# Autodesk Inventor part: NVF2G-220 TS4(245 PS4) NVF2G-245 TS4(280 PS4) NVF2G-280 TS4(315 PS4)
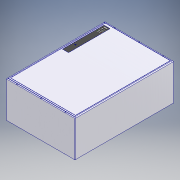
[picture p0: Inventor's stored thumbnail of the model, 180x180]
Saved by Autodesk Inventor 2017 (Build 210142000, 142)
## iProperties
Part Number: NVF2G-220 TS4(245 PS4) NVF2G-245 TS4(280 PS4) NVF2G-280 TS4(315 PS4)
Material: Типовые
Document SubType Name: Modeling
Designer: RSagdiev
Density: 1 g/cm^3
Appearance: По умолчанию
Author: RSagdiev
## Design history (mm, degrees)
sketch "Эскиз1"
  geometry: L1 (0, 0)-(44.679, 0) reference; L2 (0, 0)-(0, 56.035) reference; L3 (0, 0)-(1020, 0); L4 (1020, 0)-(1020, 370.6); L5 (1020, 370.6)-(0, 370.6); L6 (0, 370.6)-(0, 0)
  constraints: 12 end point, 3 horizontal, 2 parallel, 2 vertical, 1 perpendicular
  dimensions: "d0" = 1020 distance of L5.end L4.end; "d1" = 370.6 distance of L4.end L3.end
extrude "Выдавливание1" new body sketch "Эскиз1" stored distance "d2" = 710; taper "d3" = 0 deg
sketch "Эскиз2"
  geometry: L1 (0, 0)-(0, 1020) reference; L2 (710, 0)-(710, 1020) reference; L3 (0, 1020)-(150, 1020); L4 (710, 1020)-(710, 1008); L5 (710, 0)-(560, 0); L6 (0, 0)-(0, 12); L7 (0, 1020)-(710, 1020) reference; L8 (0, 1020)-(150, 1020); L9 (150, 1020)-(150, 1008); L10 (150, 1008)-(0, 1008); L11 (0, 1008)-(0, 1020); L12 (710, 1020)-(560, 1020); L13 (560, 1020)-(560, 1008); L14 (560, 1008)-(710, 1008); L15 (710, 1008)-(710, 1020); L16 (0, 0)-(710, 0) reference; L17 (0, 0)-(150, 0); L18 (150, 0)-(150, 12); L19 (150, 12)-(0, 12); L20 (0, 12)-(0, 0); L21 (710, 0)-(560, 0); L22 (560, 0)-(560, 12); L23 (560, 12)-(710, 12); L24 (710, 12)-(710, 0); L25 (150, 1020)-(560, 1020); L26 (0, 1008)-(0, 1020); L27 (560, 1020)-(710, 1020); L28 (710, 1008)-(710, 12); L29 (560, 0)-(150, 0); L30 (710, 12)-(710, 0); L31 (150, 0)-(0, 0); L32 (0, 12)-(0, 1008); L33 (150, 1008)-(560, 1008); L34 (150, 12)-(560, 12); 1 further point
  constraints: 60 end point, 26 parallel, 13 perpendicular, 7 horizontal
  dimensions: "d4" = 150 distance of L9.end L10.end; "d5" = 12 distance of L3.end L9.end; "d6" = 150 distance of L4.end L13.end; "d7" = 12 distance of L13.end L12.end; "d8" = 150 distance of L6.end L18.end; "d9" = 12 distance of L18.end L17.end; "d10" = 150 distance of L22.end L23.end; "d11" = 12 distance of L5.end L22.end
extrude "Выдавливание2" new body sketch "Эскиз2" distance "d12" = 4; taper "d13" = 0 deg
sketch "Эскиз3"
  geometry: L1 (690, 25)-(690, 1004); L2 (20, 1004)-(690, 1004); L3 (20, 1004)-(20, 25); L4 (20, 1004)-(690, 1004); L5 (20, 25)-(690, 25); L6 (0, 1008)-(0, 12) reference; L7 (710, 12)-(710, 1008) reference; L8 (0, 1020)-(710, 1020) reference; L9 (0, 0)-(710, 0) reference; 1 further point
  constraints: 11 end point, 2 perpendicular, 1 horizontal
  dimensions: "d162" = 20 distance between parallel lines of L6 L3 (derived); "d164" = 20 distance between parallel lines of L7 L1; "d203" = 16 distance between parallel lines of L2 L8; "d204" = 25 distance between parallel lines of L9 L5
extrude "Выдавливание3" new body sketch "Эскиз3" distance "d17" = 2; taper "d18" = 0 deg
sketch "Эскиз4"
  geometry: L1 (91, 980)-(32, 980); L2 (30, 978)-(30, 552); L3 (32, 550)-(91, 550); L4 (93, 552)-(93, 978); L5 (0, 1020)-(710, 1020) reference; L6 (0, 1008)-(0, 12) reference; A1 r 2 centre (32, 978) between (32, 980) and (30, 978); A2 r 2 centre (91, 978) between (93, 978) and (91, 980); A3 r 2 centre (91, 552) between (91, 550) and (93, 552); A4 r 2 centre (32, 552) between (30, 552) and (32, 550); 6 further points
  constraints: 8 end point, 8 point on circle, 8 tangent, 6 point on line, 4 centre point, 3 equal radius, 2 parallel, 1 horizontal, 1 perpendicular
  dimensions: "d20" = 63 distance of point (93, 550) point (30, 550); "d21" = 430 distance of point (30, 550) point (30, 980); "d24" = 2 radius of A1; "d165" = 40 distance between parallel lines of L5 L1; "d166" = 30 distance between parallel lines of L6 L2
extrude "Выдавливание4" cut sketch "Эскиз4" distance "d25" = 0.6; taper "d26" = 0 deg
sketch "Эскиз5"
  geometry: L1 (0, 1020)-(710, 1020) reference; L2 (0, 0)-(0, 1020) reference; L3 (710, 1020)-(710, 0) reference; L4 (0, 0)-(710, 0) reference; C1 r 5 at (105, 1014); C2 r 5 at (355, 1014); C3 r 5 at (105, 6); C4 r 5 at (355, 6); C5 r 5 at (605, 1014); C6 r 5 at (605, 6); 1 further point
  constraints: 6 centre point
  dimensions: "d27" = 10 diameter of C1; "d28" = 6 distance from line of C1.centre L1; "d30" = 10 diameter of C2; "d31" = 6 distance from line of C2.centre L1; "d33" = 10 diameter of C3; "d34" = 6 distance from line of L4 C3.centre; "d36" = 10 diameter of C4; "d38" = 6 distance from line of C4.centre L4; "d169" = 250 distance of C1.centre C2.centre; "d172" = 250 distance of C4.centre C3.centre (derived); "d205" = 10 diameter of C5; "d206" = 250 distance of C5.centre C2.centre (derived); "d207" = 10 diameter of C6; "d208" = 250 distance of C6.centre C4.centre (derived); "d209" = 710 distance between parallel lines of L3 L2 (derived); "d210" = 105 distance from line of L2 C1.centre (derived); "d211" = 105 distance from line of L2 C3.centre (derived)
extrude "Выдавливание5" cut sketch "Эскиз5" stored distance "d39" = 0.6; taper "d40" = 0 deg
sketch "Эскиз6"
  geometry: L1 (30, 889)-(30, 945); L2 (91, 887)-(32, 887); L3 (93, 978)-(93, 945); L4 (32, 980)-(91, 980); L5 (30, 889)-(30, 978); L6 (30, 945)-(93, 945); L7 (93, 978)-(93, 945); L8 (30, 945)-(30, 978); L9 (93, 945)-(93, 889); L10 (43.5, 956)-(79.5, 956); L11 (81.5, 958)-(81.5, 968); L12 (79.5, 970)-(43.5, 970); L13 (41.5, 968)-(41.5, 958); L14 (41.5, 956)-(81.5, 970); L15 (81.5, 956)-(41.5, 970); L16 (61.5, 933.5)-(61.5, 898.857); L17 (53.25, 933.5)-(53.25, 898.857); L18 (69.75, 898.857)-(69.75, 933.5); L19 (47, 940)-(36, 940); L20 (35, 939)-(35, 928); L21 (36, 927)-(47, 927); L22 (48, 928)-(48, 939); L23 (48, 940)-(35, 927); L24 (35, 940)-(48, 927); L25 (81.5, 958)-(81.5, 893.5); L26 (41.5, 933.5)-(88.409, 933.5); L27 (39.654, 916.179)-(85.729, 916.179); L28 (39.654, 898.857)-(84.963, 898.857); L29 (88, 928)-(88, 939); L30 (76, 927)-(87, 927); L31 (88, 940)-(75, 927); L32 (75, 940)-(88, 927); L33 (75, 939)-(75, 928); L34 (87, 940)-(76, 940); L35 (88, 910.679)-(88, 921.679); L36 (76, 909.679)-(87, 909.679); L37 (88, 922.679)-(75, 909.679); L38 (75, 922.679)-(88, 909.679); L39 (75, 921.679)-(75, 910.679); L40 (87, 922.679)-(76, 922.679); L41 (88, 893.357)-(88, 904.357); L42 (76, 892.357)-(87, 892.357); L43 (88, 905.357)-(75, 892.357); L44 (75, 905.357)-(88, 892.357); L45 (75, 904.357)-(75, 893.357); L46 (87, 905.357)-(76, 905.357); L47 (48, 893.357)-(48, 904.357); L48 (36, 892.357)-(47, 892.357); L49 (48, 905.357)-(35, 892.357); L50 (35, 905.357)-(48, 892.357); L51 (35, 904.357)-(35, 893.357); L52 (47, 905.357)-(36, 905.357); L53 (48, 910.679)-(48, 921.679); L54 (36, 909.679)-(47, 909.679); L55 (48, 922.679)-(35, 909.679); L56 (35, 922.679)-(48, 909.679); L57 (35, 921.679)-(35, 910.679); L58 (47, 922.679)-(36, 922.679); L59 (91, 887)-(32, 887); L60 (0, 1020)-(710, 1020) reference; L61 (0, 1006)-(0, 14); L62 (93, 945)-(93, 889); C1 r 6.5 at (61.5, 933.5); C2 r 6.5 at (61.5, 898.857); C3 r 6.5 at (61.5, 916.179); A1 r 2 centre (43.5, 968) between (43.5, 970) and (41.5, 968); A2 r 2 centre (79.5, 968) between (81.5, 968) and (79.5, 970); A3 r 2 centre (79.5, 958) between (79.5, 956) and (81.5, 958); A4 r 2 centre (43.5, 958) between (41.5, 958) and (43.5, 956); A5 r 8.25 centre (61.5, 933.5) between (69.75, 933.5) and (53.25, 933.5); A6 r 8.25 centre (61.5, 898.857) between (53.25, 898.857) and (69.75, 898.857); A7 r 1 centre (47, 939) between (48, 939) and (47, 940); A8 r 1 centre (47, 928) between (47, 927) and (48, 928); A9 r 1 centre (36, 928) between (35, 928) and (36, 927); A10 r 1 centre (36, 939) between (36, 940) and (35, 939); A11 r 1 centre (87, 928) between (87, 927) and (88, 928); A12 r 1 centre (87, 939) between (88, 939) and (87, 940); A13 r 1 centre (76, 939) between (76, 940) and (75, 939); A14 r 1 centre (76, 928) between (75, 928) and (76, 927); A15 r 1 centre (87, 910.679) between (87, 909.679) and (88, 910.679); A16 r 1 centre (87, 921.679) between (88, 921.679) and (87, 922.679); A17 r 1 centre (76, 921.679) between (76, 922.679) and (75, 921.679); A18 r 1 centre (76, 910.679) between (75, 910.679) and (76, 909.679); A19 r 1 centre (87, 893.357) between (87, 892.357) and (88, 893.357); A20 r 1 centre (87, 904.357) between (88, 904.357) and (87, 905.357); A21 r 1 centre (76, 904.357) between (76, 905.357) and (75, 904.357); A22 r 1 centre (76, 893.357) between (75, 893.357) and (76, 892.357); A23 r 1 centre (47, 893.357) between (47, 892.357) and (48, 893.357); A24 r 1 centre (47, 904.357) between (48, 904.357) and (47, 905.357); A25 r 1 centre (36, 904.357) between (36, 905.357) and (35, 904.357); A26 r 1 centre (36, 893.357) between (35, 893.357) and (36, 892.357); A27 r 1 centre (47, 910.679) between (47, 909.679) and (48, 910.679); A28 r 1 centre (47, 921.679) between (48, 921.679) and (47, 922.679); A29 r 1 centre (36, 921.679) between (36, 922.679) and (35, 921.679); A30 r 1 centre (36, 910.679) between (35, 910.679) and (36, 909.679); A31 r 2 centre (32, 978) between (32, 980) and (30, 978); A32 r 2 centre (91, 978) between (93, 978) and (91, 980); A33 r 2 centre (91, 889) between (91, 887) and (93, 889); A34 r 2 centre (32, 889) between (30, 889) and (32, 887); 15 further points
  constraints: 124 end point, 70 tangent, 68 point on circle, 67 point on line, 37 centre point, 21 equal radius, 15 midpoint, 15 parallel, 11 horizontal, 7 collinear, 7 perpendicular, 3 coincident, 2 vertical
  dimensions: "d43" = 35 distance between parallel lines of L4 L6; "d44" = 40 distance of L15.end L14.end; "d45" = 14 distance of L14.end L15.start; "d46" = 10 distance between parallel lines of L4 L12; "d47" = 2 radius of A1; "d48" = 11.5 distance between parallel lines of L8 L13; "d49" = 16.5 diameter of A6; "d50" = 31.5 distance between parallel lines of L1 L16; "d51" = 11.5 distance from line of L6 L16.start; "d52" = 11.85714 distance from line of L2 L16.end; "d53" = 13 diameter of C1; "d54" = 13 diameter of C2; "d55" = 13 diameter of C3; "d56" = 13 distance of L24.end L23.end; "d57" = 13 distance of L23.end L24.start; "d58" = 1 radius of A7 (derived); "d59" = 11.5 distance from line of L6 L26.start; "d60" = 11.5 distance from line of L5 L26.start; "d61" = 13 distance of L32.end L31.end; "d62" = 13 distance of L31.end L32.start; "d63" = 1 radius of A12 (derived); "d64" = 13 distance of L38.end L37.end; "d65" = 13 distance of L37.end L38.start; "d66" = 1 radius of A16 (derived); "d67" = 13 distance of L44.end L43.end; "d68" = 13 distance of L43.end L44.start; "d69" = 1 radius of A20 (derived); "d70" = 13 distance of L50.end L49.end; "d71" = 13 distance of L49.end L50.start; "d72" = 1 radius of A24 (derived); "d73" = 13 distance of L56.end L55.end; "d74" = 13 distance of L55.end L56.start; "d75" = 1 radius of A28 (derived); "d146" = 40 distance of point (81.5, 933.5) L26.start; "d147" = 4.32143 distance between parallel lines of L40 L30; "d148" = 4.32143 distance between parallel lines of L46 L36; "d149" = 93 distance between parallel lines of L2 L4; "d151" = 2 radius of A31; "d152" = 2 radius of A32; "d153" = 2 radius of A33; "d154" = 2 radius of A34; "d167" = 40 distance between parallel lines of L4 L60 (derived); "d168" = 30 distance between parallel lines of L61 L5 (derived)
extrude "Выдавливание6" new body sketch "Эскиз6" distance "d76" = 0.3; taper "d77" = 0 deg
extrude "Выдавливание7" new body sketch "Эскиз6" distance "d78" = 0.6; taper "d79" = 0 deg
sketch "Эскиз7"
  geometry: L1 (30, 945)-(93, 945) reference; L2 (30, 945)-(93, 945); L3 (93, 945)-(93, 945.1); L4 (93, 945.1)-(30, 945.1); L5 (30, 945.1)-(30, 945); 4 further points; 1 other entity
  constraints: 8 end point, 2 parallel, 1 horizontal, 1 perpendicular, 2 other
  dimensions: "d80" = 0.1 distance of L3.end L2.end
extrude "Выдавливание8" cut sketch "Эскиз7" distance "d81" = 0.3; taper "d82" = 0 deg
sketch "Эскиз8" dims "d91" = 10
  geometry: L1 (30, 945.1)-(93, 945.1) reference; C1 r 1 at (38, 950.1); C2 r 1 at (45.75, 950.1); C3 r 1 at (53.5, 950.1); C4 r 1 at (61.25, 950.1); C5 r 1 at (69, 950.1); C6 r 1 at (76.75, 950.1); C7 r 1 at (84.5, 950.1); 4 further points; 1 other entity
  constraints: 7 centre point, 1 horizontal, 13 other
  dimensions: "d83" = 2 diameter of C1; "d84" = 5 distance from line of C1.centre L1; "d85" = 8 dimension on C1.centre; "d88" = 7.75 distance of C1.centre C2.centre
extrude "Выдавливание9" join sketch "Эскиз8" distance "d93" = 0.3; taper "d94" = 0 deg
sketch "Эскиз9"
  geometry: C1 r 6.5 at (0, 0) reference; C2 r 7.5 at (0, 0); 1 further point
  constraints: 1 centre point, 1 coincident
  dimensions: "d95" = 15 diameter of C2
extrude "Выдавливание10" join sketch "Эскиз9" distance "d96" = 9.4; taper "d97" = -3 deg
sketch "Эскиз10"
  geometry: L1 (0, 7.331)-(0.619, 6.259); L2 (0.619, 6.259)-(-0.619, 6.259); L3 (-0.619, 6.259)-(0, 7.331); 2 further points
  constraints: 6 end point, 7 other
sketch "Эскиз11"
  geometry: L1 (0, 7.917)-(0.884, 6.386); L2 (0.884, 6.386)-(-0.884, 6.386); L3 (-0.884, 6.386)-(0, 7.917); 2 further points
  constraints: 6 end point, 7 other
feature "Лофт1" sketch "Эскиз10", "Эскиз11" dims "d98" = 0, "d99" = 90 deg, "d100" = 0, "d101" = 90 deg
sketch "Эскиз12"
  geometry: L1 (38.002, 934.968)-(44.222, 934.968); L2 (44.222, 934.968)-(44.222, 931.468); L3 (44.222, 931.468)-(38.002, 931.468); L4 (38.002, 931.468)-(38.002, 934.968); L5 (37.052, 917.869)-(45.907, 917.869); L6 (45.907, 917.869)-(45.907, 914.239); L7 (45.907, 914.239)-(37.052, 914.239); L8 (37.052, 914.239)-(37.052, 917.869); L9 (36.696, 900.533)-(46.053, 900.533); L10 (46.053, 900.533)-(46.053, 896.959); L11 (46.053, 896.959)-(36.696, 896.959); L12 (36.696, 896.959)-(36.696, 900.533); L13 (75.525, 900.533)-(87.077, 900.533); L14 (87.077, 900.533)-(87.077, 896.885); L15 (87.077, 896.885)-(75.525, 896.885); L16 (75.525, 896.885)-(75.525, 900.533); L17 (77.306, 917.75)-(85.5, 917.75); L18 (85.5, 917.75)-(85.5, 914.125); L19 (85.5, 914.125)-(77.306, 914.125); L20 (77.306, 914.125)-(77.306, 917.75); L21 (75.406, 935.087)-(88.456, 935.087); L22 (88.456, 935.087)-(88.456, 931.462); L23 (88.456, 931.462)-(75.406, 931.462); L24 (75.406, 931.462)-(75.406, 935.087); 1 further point
  constraints: 12 other
feature "Рельеф1" dims "d4" = 150, "d5" = 12, "d6" = 150, "d7" = 12, "d8" = 150, "d9" = 12, "d10" = 150, "d11" = 12, "d105" = 0.1, "d106" = 0
feature "Рельеф2" dims "d4" = 150, "d5" = 12, "d6" = 150, "d7" = 12, "d8" = 150, "d9" = 12, "d10" = 150, "d11" = 12, "d107" = 0.1, "d108" = 0
feature "Рельеф3" dims "d4" = 150, "d5" = 12, "d6" = 150, "d7" = 12, "d8" = 150, "d9" = 12, "d10" = 150, "d11" = 12, "d109" = 0.1, "d110" = 0
feature "Рельеф4" dims "d4" = 150, "d5" = 12, "d6" = 150, "d7" = 12, "d8" = 150, "d9" = 12, "d10" = 150, "d11" = 12, "d111" = 0.1, "d112" = 0
feature "Рельеф5" dims "d4" = 150, "d5" = 12, "d6" = 150, "d7" = 12, "d8" = 150, "d9" = 12, "d10" = 150, "d11" = 12, "d113" = 0.1, "d114" = 0
feature "Рельеф6" dims "d4" = 150, "d5" = 12, "d6" = 150, "d7" = 12, "d8" = 150, "d9" = 12, "d10" = 150, "d11" = 12, "d115" = 0.1, "d116" = 0
sketch "Эскиз13"
  geometry: L1 (-3.144, -2.347)-(-0.04, 3.728); L2 (-0.04, 3.728)-(3.298, -2.347); L3 (3.298, -2.347)-(2.096, -2.347); L4 (2.096, -2.347)-(-0.04, 1.541); L5 (-0.04, 1.541)-(-2.027, -2.347); L6 (-2.027, -2.347)-(-3.144, -2.347); L7 (-9.387, -8.657)-(8.031, -8.657); L8 (-3.144, -14.967)-(-0.04, -21.041); L9 (-0.04, -21.041)-(3.298, -14.967); L10 (3.298, -14.967)-(2.096, -14.967); L11 (2.096, -14.967)-(-0.04, -18.855); L12 (-0.04, -18.855)-(-2.027, -14.967); L13 (-2.027, -14.967)-(-3.144, -14.967); 1 further point
  constraints: 26 end point, 6 symmetric about line, 2 horizontal, 2 parallel, 2 point on line, 1 collinear
feature "Рельеф7" dims "d4" = 150, "d5" = 12, "d6" = 150, "d7" = 12, "d8" = 150, "d9" = 12, "d10" = 150, "d11" = 12, "d117" = 0.1, "d118" = 0
feature "Рельеф8" dims "d4" = 150, "d5" = 12, "d6" = 150, "d7" = 12, "d8" = 150, "d9" = 12, "d10" = 150, "d11" = 12, "d119" = 0.1, "d120" = 0
sketch "Эскиз14"
  geometry: L1 (57.729, 666.085)-(66.026, 651.714); L2 (66.026, 651.714)-(49.433, 651.714); L3 (49.433, 651.714)-(57.729, 666.085); L4 (64.599, 652.539)-(57.729, 664.437); L5 (57.729, 664.437)-(50.86, 652.539); L6 (50.86, 652.539)-(64.599, 652.539); L7 (56.902, 660.77)-(55.962, 656.96); L8 (55.962, 656.96)-(58.383, 657.129); L9 (58.383, 657.129)-(57.342, 654.813); L10 (57.342, 654.813)-(56.392, 655.24); L11 (56.392, 655.24)-(56.549, 653.01); L12 (56.549, 653.01)-(59.019, 654.059); L13 (59.019, 654.059)-(58.338, 654.365); L14 (58.338, 654.365)-(60.267, 658.001); L15 (60.267, 658.001)-(57.113, 657.818); L16 (57.113, 657.818)-(58.679, 660.77); L17 (58.679, 660.77)-(56.902, 660.77); 2 further points
  constraints: 34 end point, 2 perpendicular, 2 point on line, 1 parallel, 9 other
extrude "Выдавливание11" cut sketch "Эскиз14" distance "d121" = 0.8; taper "d122" = 0 deg
extrude "Выдавливание12" join sketch "Эскиз14" stored distance "d123" = 0.05; taper "d124" = 0 deg
sketch "Эскиз15"
  geometry: L1 (32.937, 954.361)-(54.848, 954.361); L2 (54.848, 954.361)-(54.848, 951.81); L3 (54.848, 951.81)-(32.937, 951.81); L4 (32.937, 951.81)-(32.937, 954.361); L5 (58.162, 953.617)-(88.881, 953.617); L6 (88.881, 953.617)-(88.881, 949.704); L7 (88.881, 949.704)-(58.162, 949.704); L8 (58.162, 949.704)-(58.162, 953.617); L9 (30, 945.1)-(93, 945.1) reference; C1 r 1 at (38, 950.1) reference; 7 further points; 2 other entities
  constraints: 6 other
  dimensions: "d155" = 0.71019 distance edge to line of C1 L3; "d156" = 2.93695 dimension on L4; "d157" = 4.60387 distance between parallel lines of L9 L7; "d158" = 4.11868 dimension on L6
feature "Рельеф9" sketch "Эскиз15" dims "d4" = 150, "d5" = 12, "d6" = 150, "d7" = 12, "d8" = 150, "d9" = 12, "d10" = 150, "d11" = 12, "d125" = 0.1, "d126" = 0
sketch "Эскиз17"
  geometry: L1 (54.534, 359)-(54.534, 352.001); L2 (54.534, 352.001)-(52.465, 352.001); L3 (52.465, 352.001)-(52.465, 359); L4 (52.465, 359)-(54.534, 359); 1 further point
  constraints: 2 other
feature "Рельеф10" sketch "Эскиз17" dims "d4" = 150, "d5" = 12, "d6" = 150, "d7" = 12, "d8" = 150, "d9" = 12, "d10" = 150, "d11" = 12, "d144" = 0.1, "d145" = 0
sketch "Эскиз19" dims "d179" = 10
  geometry: L1 (113.24, 333.958)-(134.375, 351.485); L2 (114.525, 332.409)-(135.66, 349.935); L3 (133.09, 353.034)-(111.955, 335.508); L4 (370.6, 1008)-(370.6, 12) reference; L5 (113.24, 323.958)-(134.375, 341.485); L6 (114.525, 322.409)-(135.66, 339.935); L7 (133.09, 343.034)-(111.955, 325.508); L8 (113.24, 313.958)-(134.375, 331.485); L9 (114.525, 312.409)-(135.66, 329.935); L10 (133.09, 333.034)-(111.955, 315.508); L11 (113.24, 303.958)-(134.375, 321.485); L12 (114.525, 302.409)-(135.66, 319.935); L13 (133.09, 323.034)-(111.955, 305.508); L14 (113.24, 293.958)-(134.375, 311.485); L15 (114.525, 292.409)-(135.66, 309.935); L16 (133.09, 313.034)-(111.955, 295.508); L17 (113.24, 283.958)-(134.375, 301.485); L18 (114.525, 282.409)-(135.66, 299.935); L19 (133.09, 303.034)-(111.955, 285.508); L20 (113.24, 273.958)-(134.375, 291.485); L21 (114.525, 272.409)-(135.66, 289.935); L22 (133.09, 293.034)-(111.955, 275.508); L23 (113.24, 263.958)-(134.375, 281.485); L24 (114.525, 262.409)-(135.66, 279.935); L25 (133.09, 283.034)-(111.955, 265.508); L26 (113.24, 253.958)-(134.375, 271.485); L27 (114.525, 252.409)-(135.66, 269.935); L28 (133.09, 273.034)-(111.955, 255.508); L29 (113.24, 243.958)-(134.375, 261.485); L30 (114.525, 242.409)-(135.66, 259.935); L31 (133.09, 263.034)-(111.955, 245.508); A1 r 2.013 centre (113.24, 333.958) between (111.955, 335.508) and (114.525, 332.409); A2 r 2.013 centre (134.375, 351.485) between (135.66, 349.935) and (133.09, 353.034); A3 r 2.013 centre (113.24, 323.958) between (111.955, 325.508) and (114.525, 322.409); A4 r 2.013 centre (134.375, 341.485) between (135.66, 339.935) and (133.09, 343.034); A5 r 2.013 centre (113.24, 313.958) between (111.955, 315.508) and (114.525, 312.409); A6 r 2.013 centre (134.375, 331.485) between (135.66, 329.935) and (133.09, 333.034); A7 r 2.013 centre (113.24, 303.958) between (111.955, 305.508) and (114.525, 302.409); A8 r 2.013 centre (134.375, 321.485) between (135.66, 319.935) and (133.09, 323.034); A9 r 2.013 centre (113.24, 293.958) between (111.955, 295.508) and (114.525, 292.409); A10 r 2.013 centre (134.375, 311.485) between (135.66, 309.935) and (133.09, 313.034); A11 r 2.013 centre (113.24, 283.958) between (111.955, 285.508) and (114.525, 282.409); A12 r 2.013 centre (134.375, 301.485) between (135.66, 299.935) and (133.09, 303.034); A13 r 2.013 centre (113.24, 273.958) between (111.955, 275.508) and (114.525, 272.409); A14 r 2.013 centre (134.375, 291.485) between (135.66, 289.935) and (133.09, 293.034); A15 r 2.013 centre (113.24, 263.958) between (111.955, 265.508) and (114.525, 262.409); A16 r 2.013 centre (134.375, 281.485) between (135.66, 279.935) and (133.09, 283.034); A17 r 2.013 centre (113.24, 253.958) between (111.955, 255.508) and (114.525, 252.409); A18 r 2.013 centre (134.375, 271.485) between (135.66, 269.935) and (133.09, 273.034); A19 r 2.013 centre (113.24, 243.958) between (111.955, 245.508) and (114.525, 242.409); A20 r 2.013 centre (134.375, 261.485) between (135.66, 259.935) and (133.09, 263.034); 13 further points
  constraints: 80 end point, 40 point on circle, 20 centre point, 4 tangent, 1 midpoint, 1 parallel, 1 vertical, 108 other
  dimensions: "d176" = 10 distance of L2.start L6.start
extrude "Выдавливание14" cut sketch "Эскиз19" distance "d181" = 10; taper "d182" = 0 deg
sketch "Эскиз20" dims "d191" = 10, "d198" = 10
  geometry: L1 (370.6, 2)-(0, 2) reference; L2 (0, 1020)-(0, 0) reference; C1 r 2 at (15, 132); C2 r 2 at (20, 132); C3 r 2 at (25, 132); C4 r 2 at (30, 132); C5 r 2 at (35, 132); C6 r 2 at (40, 132); C7 r 2 at (45, 132); C8 r 2 at (50, 132); C9 r 2 at (55, 132); C10 r 2 at (60, 132); C11 r 2 at (65, 132); C12 r 2 at (70, 132); C13 r 2 at (70, 127); C14 r 2 at (65, 127); C15 r 2 at (60, 127); C16 r 2 at (55, 127); C17 r 2 at (15, 127); C18 r 2 at (20, 127); C19 r 2 at (25, 127); C20 r 2 at (30, 127); C21 r 2 at (35, 127); C22 r 2 at (40, 127); C23 r 2 at (45, 127); C24 r 2 at (50, 127); C25 r 2 at (70, 122); C26 r 2 at (65, 122); C27 r 2 at (60, 122); C28 r 2 at (55, 122); C29 r 2 at (15, 122); C30 r 2 at (20, 122); C31 r 2 at (25, 122); C32 r 2 at (30, 122); C33 r 2 at (35, 122); C34 r 2 at (40, 122); C35 r 2 at (45, 122); C36 r 2 at (50, 122); C37 r 2 at (70, 117); C38 r 2 at (65, 117); C39 r 2 at (60, 117); C40 r 2 at (55, 117); C41 r 2 at (15, 117); C42 r 2 at (20, 117); C43 r 2 at (25, 117); C44 r 2 at (30, 117); C45 r 2 at (35, 117); C46 r 2 at (40, 117); C47 r 2 at (45, 117); C48 r 2 at (50, 117); C49 r 2 at (70, 112); C50 r 2 at (65, 112); C51 r 2 at (60, 112); C52 r 2 at (55, 112); C53 r 2 at (15, 112); C54 r 2 at (20, 112); C55 r 2 at (25, 112); C56 r 2 at (30, 112); C57 r 2 at (35, 112); C58 r 2 at (40, 112); C59 r 2 at (45, 112); C60 r 2 at (50, 112); C61 r 2 at (70, 107); C62 r 2 at (65, 107); C63 r 2 at (60, 107); C64 r 2 at (55, 107)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; 1 further point
  constraints: 240 centre point, 1 horizontal, 1 vertical, 478 other
  dimensions: "d183" = 4 diameter of C1; "d184" = 15 distance from line of L2 C1.centre; "d185" = 130 distance from line of L1 C1.centre; "d188" = 5 distance of C1.centre C2.centre; "d195" = 5 distance of C12.centre C13.centre
extrude "Выдавливание15" cut sketch "Эскиз20" distance "d200" = 15; taper "d201" = 0 deg
fillet "Сопряжение3" dims "d212" = 20
fillet "Сопряжение4" dims "d213" = 2
node "Твердое тело1"
pattern_circular "Круговой массив1" dims angle "d103" = 360 deg
node "Твердое тело2"
node "Твердое тело3"
node "Твердое тело4"
node "Твердое тело5"
